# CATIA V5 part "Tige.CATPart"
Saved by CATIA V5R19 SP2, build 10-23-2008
Part number: Tige
Bounding box of the stored display mesh (mm): x 0 to 10, y -10 to 10, z 0 to 200
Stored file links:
  C:\Users\Romain\Documents\IFMA\2A\cours\S3\Projet CFAO-IAO\IAO\Catia\Tige\Tige.CATPart
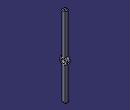
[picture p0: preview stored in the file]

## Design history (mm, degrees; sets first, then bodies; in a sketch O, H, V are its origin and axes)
Body1 (main body)
  Sketch1 on yz-plane, origin (0, 0, 0), H (0, 1, 0), V (0, 0, 1)
    line L1 (0, 0) -> (5, 0)
    point P1 (5, 0)
    line L2 (5, 0) -> (5, 200)
    point P2 (5, 200)
    line L3 (5, 200) -> (0, 200)
    point P3 (0, 200)
    point P4 (0, 200)
    point P5 (-5, 200)
    line L4 (-5, 200) -> (0, 200)
    point P6 (-5, 0)
    line L5 (-5, 0) -> (-5, 200)
    point P7 (0, 0)
    line L6 (0, 0) -> (-5, 0)
    length L1 = 5
    length L2 = 200
    horizontal: L1 H, L3 H
    vertical: L2 V
    coincidence: P3 V, O P7, P3 P4
    symmetry: P3 P4 V, P2 P5 V, L3 L4 V, P1 P6 V, L2 L5 V, O P7 V, L1 L6 V
  Pad1: profile Sketch1, direction (1, 0, 0), length 10
  Sketch2 on yz-plane, origin (0, 0, 0), H (0, 1, 0), V (0, 0, 1)
    circle A1 centre (0, 90) radius 10
    point P1 (0, 90)
    reference projected line E1 (-5, 0) -> (0, 0) from edge [face of Pad1 from Sketch1.L6 | end face of Pad1]
    radius A1 = 10
    distance E1 P1 = 90
    coincidence: P1 V
  Pad2: profile Sketch2, direction (1, 0, 0), length 10
  Fillet1: radius 2, on face of Pad2
  Fillet2: radius 2, on face of Pad2
  Fillet3: radius 2, on edge [face of Pad1 from Sketch1.L5 | face of Pad1 from Sketch1.L4]
  Fillet4: radius 2, on edge [face of Pad1 from Sketch1.L3 | face of Pad1 from Sketch1.L2]
  Sketch3 on face of Pad2, origin (0, 0, 0), H (0, -1, 0), V (0, 0, 1)
    circle A1 centre (0, 90) radius 5
    point P1 (0, 90)
    reference projected arc E1 centre (0, 90) radius 10 from (-5, 98.6603) to (-5, 81.3397) ccw from edge [face of Fillet2 | face of Pad2]
    radius A1 = 5
    distance A1 E1 = 15
    coincidence: P1 V
  Pocket1: profile Sketch3, direction (1, 0, 0), through (limit type 6)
